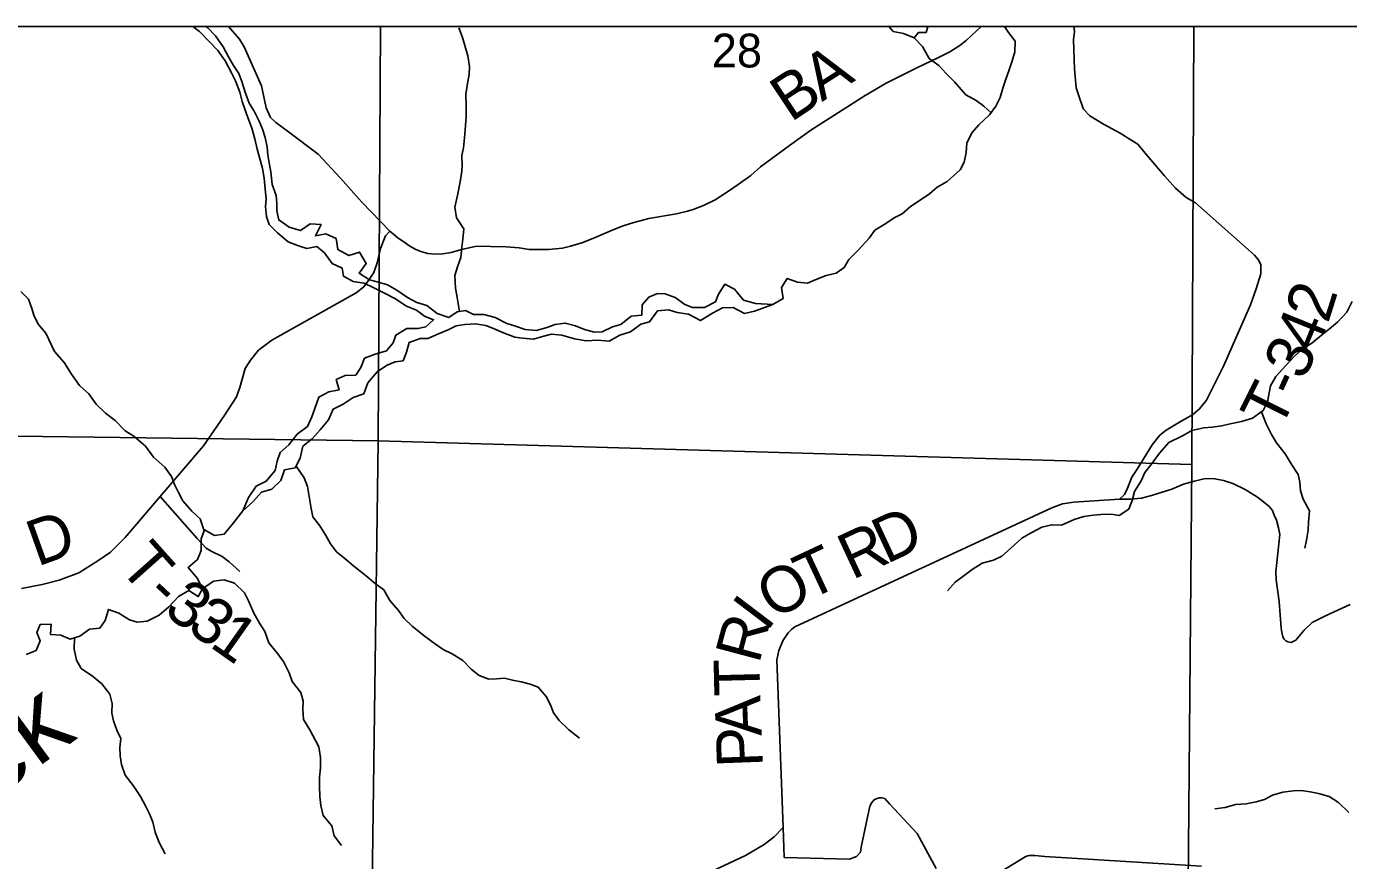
# Model space of a CAD drawing. Extents: x -20.5 to 34, y -66 to 23.9.
# Drawn here: x 6.523 to 8.16, y 19.867 to 20.9 of the extents above; entities that cross this region are included whole.
import ezdxf

# ---------------------------------------------------------------- set-up
doc = ezdxf.new("R2010")
doc.units = 0
for name, color, linetype in [('Default', 7, 'Continuous'), ('GM_X_County_Road_Text', 7, 'Continuous'), ('GM_X_County_Text', 7, 'Continuous'), ('GM_X_Minor_Lake', 7, 'Continuous'), ('GM_X_Minor_River', 7, 'Continuous'), ('GM_X_Minor_River_Text', 7, 'Continuous'), ('GM_X_Section_Text', 7, 'Continuous'), ('GM_X_State_Route', 7, 'Continuous'), ('GM_X_Township_Road_Text', 7, 'Continuous'), ('GM_X_Township_Text', 7, 'Continuous'), ('SH_Cut_Line', 7, 'Continuous'), ('SH_Data', 7, 'Continuous')]:
    doc.layers.add(name, color=color, linetype=linetype)

msp = doc.modelspace()

# ---------------------------------------------------------------- linework, layer by layer
at = {"layer": 'Default'}
for points in [[(2.1, 20.9), (8.9, 20.9), (8.9, 14.1), (2.1, 14.1)], [(6.961, 20.9), (5.9729, 20.9), (5.968, 20.4777), (5.9663, 20.3996), (6.9585, 20.3868)], [(7.9688, 20.9), (6.961, 20.9), (6.9585, 20.3868), (7.9662, 20.3576)]]:
    msp.add_lwpolyline(points, close=True, dxfattribs=at)
msp.add_lwpolyline([(8.3774, 18.8452), (8.7292, 18.8379), (8.9, 18.8361), (8.9, 20.9), (2.1, 20.9), (2.1, 19.024), (2.1138, 19.0238), (2.8866, 19.0123), (2.9847, 19.0125), (3.3332, 19.0103), (5.1839, 18.9738), (5.2343, 18.9736), (5.2893, 18.9731), (5.9456, 18.969), (5.9451, 18.8918), (6.0429, 18.8899), (6.0928, 18.889), (6.2064, 18.8869)], dxfattribs=at)
at = {"layer": 'GM_X_County_Text'}
for points in [[(7.82, 20.9), (7.8208, 20.8937), (7.8194, 20.8834), (7.8208, 20.8469), (7.823, 20.824), (7.8283, 20.808), (7.8318, 20.7974), (7.8399, 20.7892), (7.8568, 20.779), (7.8775, 20.7677), (7.8919, 20.7587), (7.8991, 20.7544), (7.9062, 20.7457), (7.9153, 20.7348), (7.9322, 20.7149), (7.9457, 20.6997), (7.9592, 20.688), (7.9706, 20.6814), (8.0362, 20.6232), (8.0438, 20.6167), (8.0487, 20.611), (8.0517, 20.6046), (8.0517, 20.5938), (8.0458, 20.5749), (8.0387, 20.5552), (8.0053, 20.4791), (7.9841, 20.4372), (7.9757, 20.4264), (7.9671, 20.4191), (7.9529, 20.4113), (7.9342, 20.4001), (7.9267, 20.3939), (7.9171, 20.3818), (7.8984, 20.3518), (7.8919, 20.3418), (7.8865, 20.3283), (7.8828, 20.3206), (7.8767, 20.3148), (7.8199, 20.311), (7.806, 20.3087), (7.7926, 20.3037), (7.4745, 20.1564), (7.4703, 20.1534), (7.4662, 20.1491), (7.4599, 20.1402), (7.4545, 20.1272), (7.452, 20.1157), (7.4599, 19.9081)], [(8.1622, 20.1843), (8.1324, 20.1704), (8.115, 20.1621), (8.1053, 20.1524), (8.0949, 20.1401), (8.0925, 20.1386), (8.0893, 20.1371), (8.0851, 20.138), (8.0824, 20.1393), (8.0804, 20.1412), (8.079, 20.1442), (8.0776, 20.1496), (8.0768, 20.1548), (8.0744, 20.188), (8.0706, 20.2147), (8.0703, 20.2246), (8.075, 20.2707), (8.0735, 20.279), (8.0712, 20.2885), (8.0683, 20.295), (8.0661, 20.3004), (8.0618, 20.3055), (8.0549, 20.3115), (8.0475, 20.3169), (8.0324, 20.3265), (8.0171, 20.3339), (8.0052, 20.3379), (7.9948, 20.3398), (7.9882, 20.3402), (7.981, 20.3396), (7.9695, 20.3369), (7.956, 20.3331), (7.9413, 20.3272), (7.916, 20.319), (7.9039, 20.316), (7.8903, 20.3145), (7.8767, 20.3148)], [(6.7871, 20.2249), (6.7736, 20.2372), (6.7651, 20.2435), (6.7516, 20.2501), (6.7454, 20.2541), (6.7342, 20.2661), (6.6884, 20.318)], [(7.4599, 19.9081), (7.4613, 19.8711), (7.5421, 19.8689), (7.5508, 19.8721), (7.5556, 19.8776), (7.5564, 19.8838), (7.5672, 19.9345), (7.5696, 19.9392), (7.5725, 19.9424), (7.5752, 19.9437), (7.5789, 19.9448), (7.5822, 19.9448), (7.5857, 19.9441), (7.5917, 19.9372), (7.6261, 19.9008), (7.6494, 19.8574)], [(7.1423, 19.7463), (7.4133, 19.8732), (7.4366, 19.8872), (7.4489, 19.8967), (7.4599, 19.9081)], [(7.7076, 19.8399), (7.7596, 19.8718), (7.7625, 19.873), (7.7649, 19.8734), (7.7716, 19.8734), (7.7839, 19.8722), (7.9782, 19.86)]]:
    msp.add_lwpolyline(points, dxfattribs=at)
at = {"layer": 'GM_X_Minor_Lake'}
for points in [[(5.9663, 20.3996), (6.9585, 20.3868), (6.9446, 19.3763), (5.9493, 19.3913), (5.9508, 19.4767)], [(6.9585, 20.3868), (7.9662, 20.3576), (7.9573, 19.3612), (6.9446, 19.3763)]]:
    msp.add_lwpolyline(points, close=True, dxfattribs=at)
at = {"layer": 'GM_X_Minor_River'}
for points in [[(7.591, 20.9), (7.5963, 20.8937), (7.6092, 20.8913), (7.6222, 20.8858)], [(7.6222, 20.8858), (7.6274, 20.8923), (7.6369, 20.8925), (7.6393, 20.9)]]:
    msp.add_lwpolyline(points, dxfattribs=at)
at = {"layer": 'GM_X_Minor_River_Text'}
for points in [[(6.7289, 20.9), (6.737, 20.8939), (6.7486, 20.8816), (6.7598, 20.87), (6.7688, 20.8573), (6.7766, 20.8426), (6.7817, 20.8325), (6.7869, 20.8185), (6.7897, 20.8072), (6.7933, 20.7974), (6.7969, 20.7872), (6.8017, 20.774), (6.8057, 20.7608), (6.8086, 20.7479), (6.8122, 20.7347), (6.8151, 20.7241), (6.8172, 20.712), (6.8185, 20.6984), (6.8195, 20.6866), (6.8189, 20.6771), (6.8198, 20.6646), (6.8234, 20.6548), (6.8335, 20.6444), (6.847, 20.6332), (6.8596, 20.6285), (6.8699, 20.6252), (6.8824, 20.6273), (6.892, 20.6195), (6.9013, 20.6064), (6.9139, 20.6006), (6.9153, 20.5907), (6.9275, 20.5841), (6.9408, 20.582), (6.9531, 20.5762), (6.9669, 20.5692), (6.9791, 20.5629), (6.9933, 20.5537), (7.0056, 20.5486), (7.0156, 20.5411), (7.027, 20.5368), (7.0173, 20.5279), (7.0075, 20.5258), (6.9938, 20.526), (6.9803, 20.5178), (6.977, 20.5083), (6.9688, 20.4983), (6.9545, 20.4942), (6.9413, 20.4891), (6.9369, 20.4776), (6.9306, 20.468), (6.9173, 20.4678), (6.9064, 20.4627), (6.91, 20.4499), (6.8971, 20.4477), (6.8847, 20.4411), (6.8797, 20.427), (6.876, 20.4167), (6.8709, 20.4048), (6.8578, 20.3951), (6.8478, 20.3817), (6.8369, 20.3724), (6.8333, 20.3617), (6.8308, 20.3503), (6.8197, 20.3368), (6.8072, 20.3309), (6.7976, 20.3167), (6.7907, 20.3003)], [(7.447, 20.5555), (7.4257, 20.557), (7.4109, 20.561), (7.3996, 20.5748), (7.3878, 20.5807), (7.38, 20.5684), (7.3763, 20.5589), (7.3624, 20.5518), (7.3476, 20.5519), (7.3381, 20.5556), (7.3261, 20.5645), (7.3139, 20.5688), (7.3044, 20.5691), (7.2935, 20.5647), (7.2853, 20.5551), (7.2847, 20.5426), (7.2718, 20.5412), (7.2587, 20.5308), (7.2485, 20.5279), (7.2357, 20.522), (7.2262, 20.5215), (7.214, 20.5247), (7.2029, 20.5291), (7.19, 20.5327), (7.1775, 20.5309), (7.1673, 20.527), (7.1544, 20.5233), (7.1404, 20.5246), (7.1285, 20.529), (7.1178, 20.5322), (7.1033, 20.5396), (7.0892, 20.5431), (7.0763, 20.5433), (7.0663, 20.5481), (7.0561, 20.5467), (7.046, 20.5394), (7.0315, 20.5444), (7.0188, 20.5545), (7.0062, 20.5581), (6.9947, 20.5643), (6.9816, 20.5736), (6.9697, 20.5802), (6.9598, 20.5831), (6.9476, 20.5863), (6.9349, 20.5944), (6.9435, 20.6063), (6.9353, 20.6206), (6.922, 20.6162), (6.9082, 20.6236), (6.9065, 20.6372), (6.8935, 20.6431), (6.8806, 20.6406), (6.8876, 20.6547), (6.8739, 20.6557), (6.8623, 20.6471), (6.8482, 20.6514), (6.8351, 20.6603), (6.8326, 20.6717), (6.8329, 20.6812), (6.8319, 20.6906), (6.8272, 20.7042), (6.8254, 20.7201), (6.8233, 20.7311), (6.8216, 20.7409), (6.8207, 20.7504), (6.8182, 20.7625), (6.815, 20.7727), (6.811, 20.7825), (6.8048, 20.7949), (6.7985, 20.805), (6.7941, 20.8175), (6.7893, 20.8318), (6.7857, 20.8416), (6.7791, 20.8514), (6.7729, 20.8623), (6.7662, 20.8747), (6.7569, 20.8882), (6.7472, 20.8983), (6.7452, 20.9)], [(7.059, 20.5471), (7.0562, 20.5642), (7.0541, 20.5759), (7.0534, 20.5915), (7.0567, 20.6022), (7.0607, 20.614), (7.062, 20.6265), (7.0633, 20.6364), (7.0646, 20.6493), (7.0553, 20.6628), (7.0532, 20.6761), (7.0571, 20.6925), (7.0595, 20.7054), (7.0616, 20.7176), (7.0622, 20.7271), (7.062, 20.74), (7.0641, 20.7495), (7.0654, 20.762), (7.066, 20.7719), (7.0672, 20.7879), (7.0674, 20.8011), (7.0671, 20.8163), (7.0688, 20.8292), (7.0709, 20.8403), (7.0715, 20.8502), (7.0694, 20.8634), (7.0658, 20.8762), (7.0629, 20.8861), (7.0582, 20.8981)], [(7.447, 20.5555), (7.4598, 20.5629), (7.4577, 20.5769), (7.4651, 20.588), (7.4777, 20.5833), (7.4899, 20.582), (7.4997, 20.5863), (7.5132, 20.5915), (7.5257, 20.5943), (7.5355, 20.6013), (7.5414, 20.6113), (7.5533, 20.6232), (7.5664, 20.6379), (7.5734, 20.6475), (7.5873, 20.6561), (7.5975, 20.663), (7.6073, 20.6678), (7.6177, 20.677), (7.6309, 20.6856), (7.641, 20.6926), (7.6508, 20.7011), (7.6632, 20.7078), (7.6793, 20.7224), (7.684, 20.732), (7.6865, 20.7438), (7.6874, 20.756), (7.694, 20.7686), (7.7022, 20.7782), (7.7157, 20.7906), (7.7235, 20.8013), (7.7286, 20.812), (7.7326, 20.8246), (7.7358, 20.8345), (7.7395, 20.8448), (7.7434, 20.8574), (7.7467, 20.8685), (7.7472, 20.8818), (7.7391, 20.8923), (7.7343, 20.9)], [(7.7175, 20.793), (7.7087, 20.8011), (7.6991, 20.8081), (7.6861, 20.8151), (7.6721, 20.8312), (7.6617, 20.8417), (7.6528, 20.8518), (7.6409, 20.8603), (7.6326, 20.875), (7.6222, 20.8858), (7.6092, 20.8913), (7.5963, 20.8937), (7.591, 20.9)], [(6.7428, 20.2756), (6.738, 20.2903), (6.7276, 20.2996), (6.7164, 20.3127), (6.7109, 20.3229), (6.7062, 20.3327), (6.7022, 20.3428), (6.6941, 20.3541), (6.6802, 20.3667), (6.6701, 20.3802), (6.6558, 20.3925), (6.6451, 20.3992), (6.6324, 20.4119), (6.6204, 20.4212), (6.6092, 20.4323), (6.5999, 20.4451), (6.5883, 20.4555), (6.5786, 20.4694), (6.5692, 20.484), (6.5576, 20.4975), (6.5466, 20.5201), (6.5377, 20.5309), (6.5322, 20.5411), (6.5294, 20.5509), (6.5254, 20.5622), (6.5158, 20.5719)], [(6.7907, 20.3003), (6.803, 20.3115), (6.8138, 20.3231), (6.8267, 20.3271), (6.8379, 20.3379), (6.8422, 20.3508), (6.8554, 20.3533), (6.8617, 20.3652), (6.8649, 20.3801), (6.8765, 20.3894), (6.8866, 20.4005), (6.8966, 20.4128), (6.9024, 20.4262), (6.9149, 20.4321), (6.9273, 20.4407), (6.9405, 20.4451), (6.9456, 20.4588), (6.9575, 20.4726), (6.9695, 20.4804), (6.9793, 20.4848), (6.9891, 20.4861), (6.9935, 20.4968), (6.9967, 20.5086), (7.0103, 20.5134), (7.0198, 20.5135), (7.033, 20.5194), (7.0451, 20.5242), (7.0549, 20.5293), (7.0655, 20.531), (7.0787, 20.5319), (7.0917, 20.5295), (7.1012, 20.5259), (7.1135, 20.5204), (7.1276, 20.5153), (7.1371, 20.5139), (7.1508, 20.5127), (7.1618, 20.5159), (7.1731, 20.5191), (7.1857, 20.5178), (7.2013, 20.5131), (7.2158, 20.5107), (7.2302, 20.5117), (7.2443, 20.5104), (7.2578, 20.5178), (7.271, 20.5218), (7.2838, 20.5315), (7.2944, 20.534), (7.3044, 20.5478), (7.318, 20.5492), (7.3287, 20.5456), (7.3428, 20.5435), (7.3577, 20.5358), (7.3724, 20.5451), (7.3848, 20.5514), (7.3981, 20.552), (7.4119, 20.5447), (7.4244, 20.5475), (7.447, 20.5555)], [(8.1646, 20.5592), (8.1583, 20.5462), (8.1464, 20.5339), (8.1367, 20.5254), (8.1243, 20.5157), (8.1146, 20.5076), (8.1044, 20.5017), (8.0939, 20.4921), (8.0824, 20.4801), (8.0701, 20.4666), (8.0634, 20.4551), (8.06, 20.4353), (8.0544, 20.4243), (8.0413, 20.4149), (8.0277, 20.4109), (8.0137, 20.408), (8.0035, 20.4056), (7.9914, 20.4039), (7.9808, 20.403), (7.966, 20.3997), (7.9547, 20.393), (7.9378, 20.3848), (7.9259, 20.3717), (7.9158, 20.3575), (7.908, 20.3475), (7.9033, 20.3372), (7.8951, 20.3242), (7.8923, 20.3131), (7.8879, 20.3024), (7.8763, 20.2943), (7.8664, 20.296), (7.8535, 20.2958), (7.844, 20.2949), (7.8323, 20.2932), (7.8202, 20.2896), (7.8047, 20.2825), (7.7926, 20.283), (7.7805, 20.2798), (7.7673, 20.2728), (7.7556, 20.2665), (7.7414, 20.2534), (7.7306, 20.2441), (7.7204, 20.239), (7.7064, 20.2353), (7.694, 20.2276), (7.6843, 20.2202), (7.673, 20.212), (7.6637, 20.2013)], [(8.0524, 20.4228), (8.0581, 20.408), (8.0648, 20.3945), (8.0711, 20.3843), (8.0819, 20.3708), (8.089, 20.3584), (8.0979, 20.3453), (8.1, 20.3355), (8.1009, 20.3248), (8.1041, 20.3147), (8.112, 20.3), (8.1107, 20.2863), (8.1101, 20.2764), (8.108, 20.2639), (8.1059, 20.254)], [(6.8567, 20.3556), (6.8667, 20.341), (6.8706, 20.3305), (6.8736, 20.313), (6.8753, 20.3032), (6.8774, 20.2926), (6.8859, 20.2814), (6.8937, 20.2697), (6.8992, 20.2592), (6.9066, 20.2495), (6.9173, 20.2409), (6.9304, 20.2298), (6.9416, 20.2208), (6.9547, 20.2101), (6.9654, 20.2023), (6.9729, 20.1891), (6.9833, 20.1768), (6.9907, 20.167), (7.0004, 20.1573), (7.0154, 20.1454), (7.0292, 20.135), (7.0388, 20.1284), (7.0499, 20.1232), (7.0633, 20.1147), (7.0734, 20.1043), (7.0834, 20.0961), (7.0952, 20.0917), (7.1047, 20.0923), (7.1146, 20.0928), (7.1245, 20.0903), (7.1355, 20.0886), (7.1466, 20.0854), (7.1565, 20.0817), (7.1666, 20.0701), (7.1717, 20.06), (7.1753, 20.0502), (7.1823, 20.0404), (7.1946, 20.0289), (7.2077, 20.0188)], [(6.6202, 20.1643), (6.6241, 20.178), (6.6371, 20.1733), (6.6502, 20.1652), (6.6597, 20.1623), (6.6722, 20.1636), (6.6869, 20.1711), (6.6989, 20.1811), (6.7112, 20.1943), (6.724, 20.2017), (6.7355, 20.1939), (6.7406, 20.2035), (6.7347, 20.2163), (6.7231, 20.2301), (6.7347, 20.2398), (6.7391, 20.2512), (6.7392, 20.2653), (6.7432, 20.2767), (6.7555, 20.2697), (6.7676, 20.2711), (6.7791, 20.2853), (6.7907, 20.3003)], [(6.7406, 20.2036), (6.7545, 20.2132), (6.7674, 20.2149), (6.7804, 20.2106), (6.7927, 20.1986), (6.7978, 20.1889), (6.8042, 20.1734), (6.8112, 20.161), (6.8178, 20.1509), (6.823, 20.1369), (6.8339, 20.1231), (6.8413, 20.1129), (6.8479, 20.0994), (6.8519, 20.0888), (6.8624, 20.0753), (6.8656, 20.0644), (6.865, 20.0549), (6.866, 20.0416), (6.8738, 20.0289), (6.8848, 20.0078), (6.8869, 19.9946), (6.8867, 19.982), (6.8858, 19.9703), (6.8856, 19.9593), (6.8862, 19.9464), (6.8871, 19.9354), (6.89, 19.9229), (6.9009, 19.9102), (6.9037, 19.8977), (6.913, 19.8857)], [(6.5222, 20.1224), (6.5346, 20.1272), (6.5397, 20.1394), (6.5354, 20.1496), (6.5398, 20.1595), (6.5531, 20.1598), (6.5525, 20.1472), (6.5654, 20.1463), (6.5769, 20.1412), (6.589, 20.1448), (6.6006, 20.1537), (6.6135, 20.1547), (6.6202, 20.1643)], [(6.5822, 20.1428), (6.5817, 20.1287), (6.5846, 20.1151), (6.5904, 20.105), (6.6043, 20.0953), (6.6162, 20.0861), (6.6259, 20.0733), (6.6287, 20.0616), (6.6286, 20.0498), (6.6306, 20.04), (6.6346, 20.0287), (6.6397, 20.0182), (6.6384, 20.0071), (6.6386, 19.9969), (6.6406, 19.9859), (6.645, 19.9727), (6.6547, 19.96), (6.6641, 19.9465), (6.67, 19.9348), (6.6751, 19.925), (6.6794, 19.9145), (6.6823, 19.9024), (6.6871, 19.8896), (6.6945, 19.8756)], [(8.1608, 19.9267), (8.148, 19.939), (8.1361, 19.9464), (8.1231, 19.9503), (8.1129, 19.9521), (8.1014, 19.9538), (8.092, 19.9536), (8.0787, 19.9519), (8.0659, 19.9479), (8.0561, 19.9428), (8.0459, 19.94), (8.0334, 19.9375), (8.0201, 19.9365), (8.0076, 19.9329), (7.9948, 19.9312)]]:
    msp.add_lwpolyline(points, dxfattribs=at)
at = {"layer": 'GM_X_State_Route'}
for points in [[(6.9726, 20.6464), (6.9379, 20.6823), (6.9116, 20.7123), (6.8838, 20.7418), (6.8472, 20.7696), (6.8317, 20.781), (6.8249, 20.7871), (6.8194, 20.799), (6.8139, 20.8263), (6.7925, 20.8748), (6.7867, 20.8841), (6.7731, 20.9)], [(7.7053, 20.9), (7.6868, 20.8826), (7.6787, 20.8764), (7.6665, 20.8685), (7.6514, 20.8611), (7.6255, 20.8489), (7.5876, 20.8298), (7.5615, 20.8146), (7.4942, 20.7716), (7.4676, 20.7527), (7.4319, 20.726), (7.4198, 20.7154), (7.4043, 20.7043), (7.391, 20.6953), (7.3756, 20.6854), (7.3611, 20.6781), (7.3486, 20.6731), (7.3414, 20.6711), (7.3277, 20.668), (7.2934, 20.6621), (7.2748, 20.657), (7.2617, 20.653), (7.2502, 20.6487), (7.2241, 20.6372), (7.2107, 20.632), (7.1967, 20.6277), (7.1867, 20.6256), (7.178, 20.6246), (7.1699, 20.6236), (7.1571, 20.6236), (7.1454, 20.6239), (7.1329, 20.6257), (7.1167, 20.6269), (7.098, 20.6275), (7.0895, 20.628), (7.0786, 20.6274), (7.0615, 20.6238), (7.0488, 20.6202), (7.0383, 20.6183), (7.0294, 20.6179), (7.0199, 20.6187), (7.0123, 20.621), (7.0048, 20.6239), (6.9976, 20.6277), (6.9918, 20.6319), (6.9826, 20.6384), (6.9726, 20.6464)], [(6.5165, 20.204), (6.5423, 20.209), (6.5631, 20.2144), (6.5877, 20.2236), (6.611, 20.2381), (6.6268, 20.2491), (6.6451, 20.2673), (6.6884, 20.318), (6.7418, 20.3806), (6.7677, 20.418), (6.7828, 20.4415), (6.7868, 20.453), (6.7936, 20.4763), (6.8002, 20.4867), (6.8099, 20.499), (6.8268, 20.5115), (6.931, 20.5702), (6.9404, 20.5776), (6.9471, 20.5865), (6.9529, 20.5954), (6.9571, 20.6071), (6.9612, 20.6249), (6.9673, 20.6405), (6.9726, 20.6464)]]:
    msp.add_lwpolyline(points, dxfattribs=at)
at = {"layer": 'SH_Cut_Line'}
msp.add_lwpolyline([(8.0662, 14.9881), (8.0784, 15.8902), (8.0825, 16.3121), (8.087, 16.6605), (8.0955, 17.3258), (8.2289, 17.3235), (8.271, 17.3227), (8.5216, 17.3182), (8.9, 17.3115), (8.9, 20.9), (2.1, 20.9), (2.1, 14.4131)], dxfattribs=at)
at = {"layer": 'SH_Data'}
msp.add_line((2.1, 20.9), (8.9, 20.9), dxfattribs=at)

# ---------------------------------------------------------------- texts
at = {"layer": 'GM_X_County_Road_Text'}
msp.add_text('Creek', height=0.0947, rotation=36.301, dxfattribs=at).set_placement((6.3146, 19.819))
at = {"layer": 'GM_X_Section_Text'}
for s, rotation, p in [('2', 72.4378, (8.1347, 20.5312)), ('4', 67.9867, (8.1199, 20.4942)), ('3', 66.2564, (8.1051, 20.4604)), ('T', 63.4771, (8.0752, 20.3985)), ('-', 65.3742, (8.095, 20.4384)), ('D', 24.981, (7.5878, 20.2339)), ('R', 24.9797, (7.5455, 20.2142)), ('T', 311.7089, (6.6356, 20.23)), ('T', 25.0201, (7.4911, 20.1888)), ('O', 30.4208, (7.4492, 20.1642)), ('-', 316.9331, (6.6678, 20.1943)), ('3', 324.4433, (6.6909, 20.1734)), ('3', 324.8782, (6.7196, 20.1529)), ('I', 52.8179, (7.4395, 20.1495)), ('1', 324.8759, (6.748, 20.1329)), ('R', 75.099, (7.4301, 20.1096)), ('T', 91.423, (7.4316, 20.0713)), ('A', 92.1643, (7.4335, 20.0216)), ('P', 92.1767, (7.4349, 19.9833))]:
    msp.add_text(s, height=0.0568, rotation=rotation, dxfattribs=at).set_placement(p)
at = {"layer": 'GM_X_Township_Road_Text'}
for s, rotation, p in [('A', 32.5089, (7.5079, 20.8063)), ('B', 33.624, (7.4693, 20.7806)), ('D', 19.7107, (6.5361, 20.2309))]:
    msp.add_text(s, height=0.0568, rotation=rotation, dxfattribs=at).set_placement(p)
at = {"layer": 'GM_X_Township_Text'}
msp.add_text('28', height=0.04186, rotation=0, dxfattribs=at).set_placement((7.3715, 20.8492))

doc.saveas('drawing.dxf')
